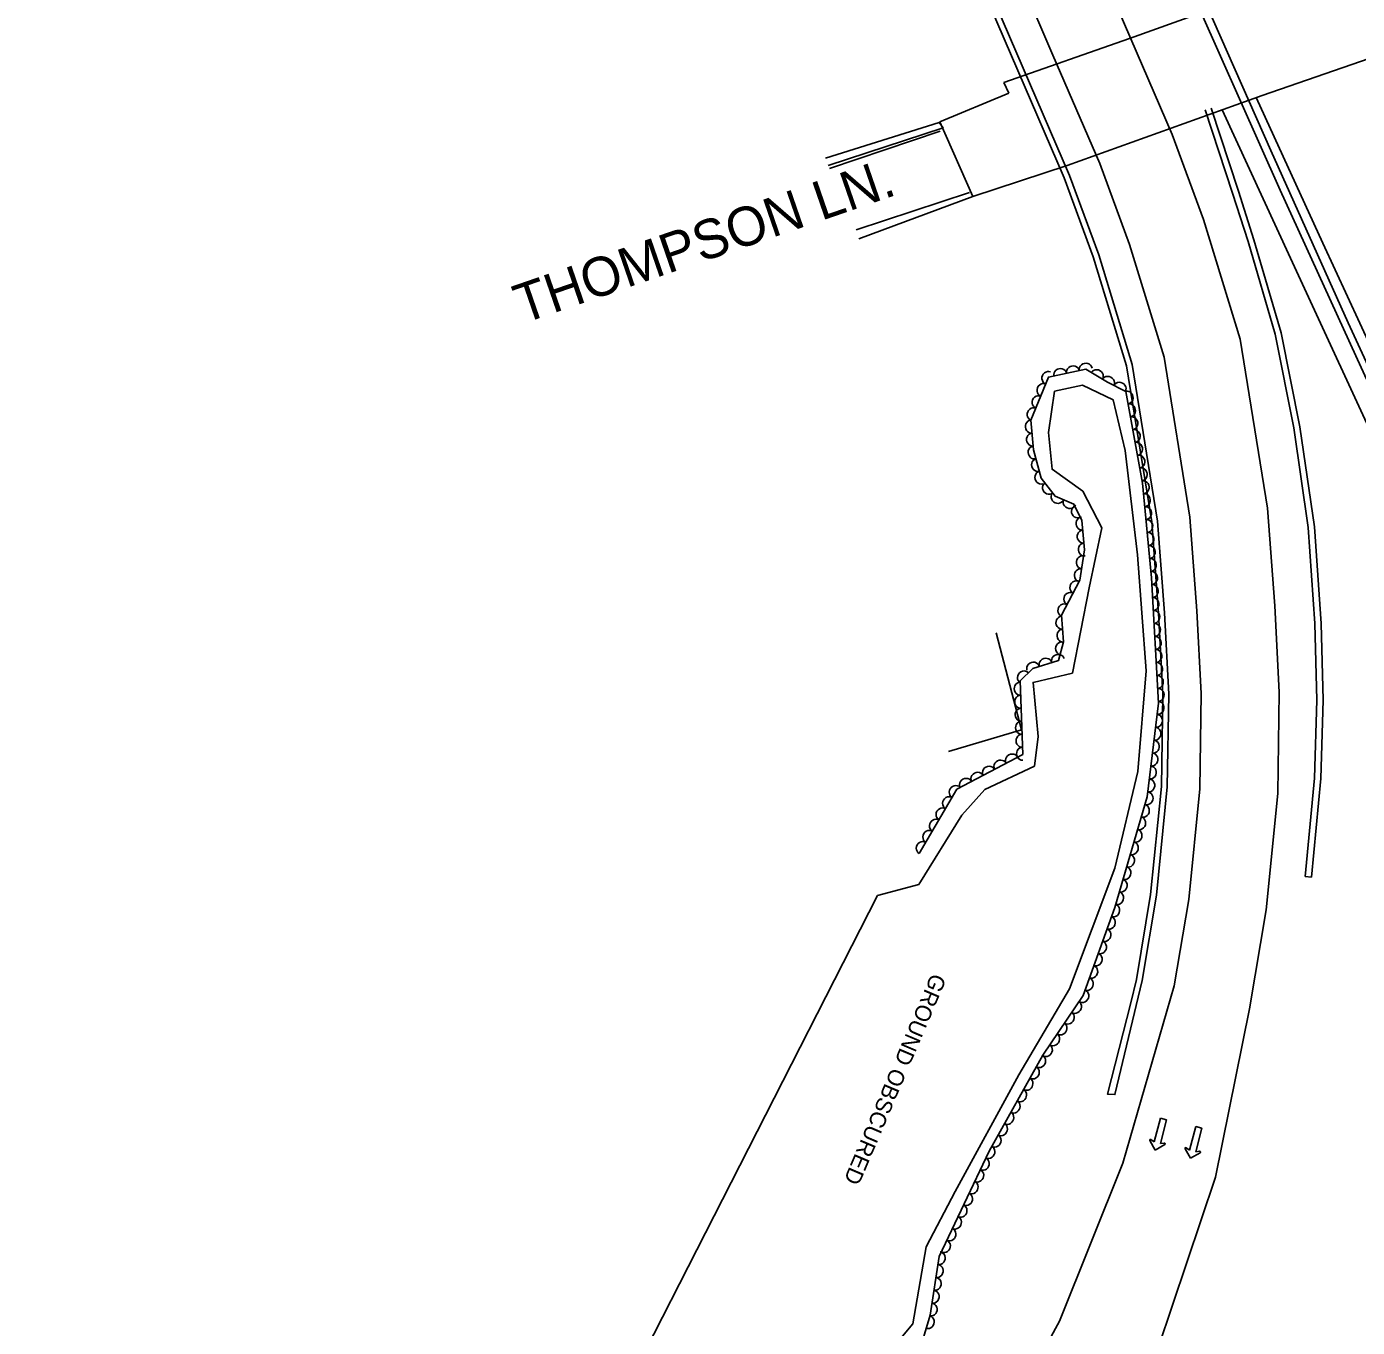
# Model space of a CAD drawing. Extents: x 1746719 to 1766531, y 631721 to 662391.
# Drawn here: x 1754626.9 to 1755036.1, y 647759.3 to 648159.2 of the extents above; entities that cross this region are included whole.
import ezdxf

# ---------------------------------------------------------------- set-up
doc = ezdxf.new("R2010")
doc.units = 0
for name, color, linetype in [('SURVEY - AERIAL SURVEY - Photo Control - Points - Elevations', 7, 'Continuous'), ('SURVEY - AERIAL SURVEY - Photo Control - Points - Locators', 7, 'Continuous'), ('SURVEY - AERIAL SURVEY - Photo Control - Points - Numbers', 7, 'Continuous'), ('SURVEY - AERIAL SURVEY - Photo Control with Text', 7, 'Continuous'), ('SURVEY - CENTERLINE - Existing Roads Curve Text', 7, 'Continuous'), ('SURVEY - CENTERLINE - Existing Roads Text', 7, 'Continuous'), ('SURVEY - CONTROL - Points - Numbers', 7, 'Continuous')]:
    doc.layers.add(name, color=color, linetype=linetype)

msp = doc.modelspace()

# ---------------------------------------------------------------- linework, layer by layer
at = {"layer": 'SURVEY - AERIAL SURVEY - Photo Control - Points - Elevations'}
for points in [[(1754626.92, 649017.27), (1754709.95, 648778.72), (1754733.03, 648713.46), (1754751.76, 648662.58), (1754773.93, 648603.83), (1754794.84, 648551.03), (1754823.16, 648481.11), (1754839.71, 648443.33), (1754863.44, 648389.05), (1754891.92, 648325.15), (1754920.31, 648262.45), (1754945.87, 648203.41), (1754964.57, 648159.87), (1754979.21, 648126.03), (1754988.86, 648099.84), (1755000.1, 648063.05), (1755008.46, 648011.18), (1755010.74, 647981.16), (1755012.12, 647954.58), (1755011.65, 647923.49), (1755008.06, 647887.7), (1755002.99, 647857.3)], [(1754923.83, 648193.91), (1754942.53, 648150.37), (1754956.92, 648117.11), (1754966.11, 648092.18), (1754976.67, 648057.61), (1754984.6, 648008.36), (1754986.79, 647979.62), (1754988.11, 647954.14), (1754987.66, 647924.88), (1754984.26, 647890.87), (1754979.83, 647864.32)], [(1755004.97, 648137.37), (1755025.54, 648092.61), (1755055.82, 648027.06), (1755078.02, 647978.11), (1755103.02, 647921.72), (1755129.6, 647862.19), (1755152.75, 647809.59), (1755172.94, 647764.12)], [(1754994.59, 648133.62), (1755015.55, 648088.01), (1755045.82, 648022.48), (1755067.98, 647973.61), (1755092.97, 647917.25), (1755119.54, 647857.74), (1755142.69, 647805.14), (1755162.88, 647759.66)], [(1754873.78, 648115.58), (1754907.89, 648126.99)], [(1754916.82, 648108.16), (1754881.96, 648096.73)], [(1754979.83, 647864.32), (1754963.96, 647809.85), (1754944.5, 647761.3), (1754906.27, 647690.97), (1754872.82, 647629.82)], [(1755002.99, 647857.3), (1754992.52, 647805.51), (1754974.85, 647753.02), (1754904.16, 647615.22)]]:
    msp.add_lwpolyline(points, dxfattribs=at)
at = {"layer": 'SURVEY - AERIAL SURVEY - Photo Control - Points - Locators'}
for p, q in [((1754973.65, 647816.33), (1754975.56, 647823.6)), ((1754975.56, 647823.6), (1754973.65, 647816.33)), ((1754977.47, 647823.1), (1754975.55, 647815.83)), ((1754977.47, 647823.1), (1754975.55, 647815.83)), ((1754975.56, 647823.6), (1754977.47, 647823.1)), ((1754977.47, 647823.1), (1754975.56, 647823.6)), ((1754984.51, 647813.8), (1754986.42, 647821.08)), ((1754986.42, 647821.08), (1754984.51, 647813.8)), ((1754988.32, 647820.58), (1754986.41, 647813.3)), ((1754988.32, 647820.58), (1754986.41, 647813.3)), ((1754986.42, 647821.08), (1754988.32, 647820.58)), ((1754988.32, 647820.58), (1754986.42, 647821.08)), ((1754974, 647813.83), (1754972.31, 647816.75)), ((1754974, 647813.83), (1754972.31, 647816.75)), ((1754972.67, 647817.07), (1754973.65, 647816.33)), ((1754973.65, 647816.33), (1754972.67, 647817.07)), ((1754976.92, 647815.53), (1754974, 647813.83)), ((1754974, 647813.83), (1754976.92, 647815.53)), ((1754975.55, 647815.83), (1754976.77, 647815.99)), ((1754975.55, 647815.83), (1754976.77, 647815.99)), ((1754984.86, 647811.31), (1754983.17, 647814.23)), ((1754984.86, 647811.31), (1754983.17, 647814.23)), ((1754983.53, 647814.55), (1754984.51, 647813.8)), ((1754984.51, 647813.8), (1754983.53, 647814.55)), ((1754986.41, 647813.3), (1754987.62, 647813.47)), ((1754986.41, 647813.3), (1754987.62, 647813.47)), ((1754987.78, 647813.01), (1754984.86, 647811.31)), ((1754984.86, 647811.31), (1754987.78, 647813.01))]:
    msp.add_line(p, q, dxfattribs=at)
for points in [[(1754989.49, 648166.25), (1755009.5, 648121.07), (1755033.31, 648068.13), (1755056.92, 648017.04), (1755088.07, 647952.49), (1755086.25, 647951.41), (1755076.05, 647972.49), (1755060.21, 648004.32), (1755035.62, 648058.01), (1755012.44, 648108.93), (1754981.51, 648178.28)], [(1754888.59, 647892.11), (1754901.25, 647895.45), (1754914.5, 647916.75), (1754921.56, 647924.64), (1754936.83, 647931.87), (1754937.93, 647941), (1754936.43, 647957.6), (1754948.49, 647960.47), (1754953.64, 647986.68), (1754957.52, 648005.09), (1754951.69, 648016.42), (1754942.28, 648023.12), (1754941.11, 648034.45), (1754943.01, 648047.07), (1754951.65, 648048.92), (1754961.07, 648044.43), (1754964.71, 648028.91), (1754968.52, 647996.83), (1754971.19, 647961.11), (1754968.64, 647930.23), (1754961.51, 647900.54), (1754947.6, 647863.41), (1754932, 647836.97), (1754912.47, 647801.13), (1754903.58, 647784.14), (1754899.41, 647760.42), (1754886.88, 647745.47)], [(1754803.95, 647726.12), (1754888.59, 647892.11)]]:
    msp.add_lwpolyline(points, dxfattribs=at)
for centre, start, end in [((1754972.52, 647816.88), 52.7863, 210.2346), ((1754972.52, 647816.88), 52.7863, 210.2346), ((1754976.8, 647815.75), 300.2346, 97.7278), ((1754976.8, 647815.75), 300.2346, 97.7278), ((1754983.38, 647814.35), 52.7863, 210.2346), ((1754983.38, 647814.35), 52.7863, 210.2346), ((1754987.66, 647813.22), 300.2346, 97.7278), ((1754987.66, 647813.22), 300.2346, 97.7278)]:
    msp.add_arc(centre, 0.246, start, end, dxfattribs=at)
at = {"layer": 'SURVEY - AERIAL SURVEY - Photo Control - Points - Numbers'}
for points in [[(1754914.65, 648189.95), (1754933.35, 648146.41), (1754947.63, 648113.39), (1754956.62, 648088.99), (1754966.91, 648055.34), (1754974.66, 648007.18), (1754976.81, 647978.98), (1754978.11, 647953.96), (1754977.67, 647925.45), (1754974.34, 647892.2), (1754969.96, 647865.96)], [(1754913, 648189.24), (1754931.7, 648145.7), (1754945.96, 648112.73), (1754954.92, 648088.42), (1754965.15, 648054.94), (1754972.88, 648006.97), (1754975.02, 647978.87), (1754976.31, 647953.93), (1754975.88, 647925.55), (1754972.56, 647892.43), (1754968.19, 647866.25)], [(1755020.13, 647897.94), (1755022.96, 647928.14), (1755023.68, 647952.09), (1755023.03, 647975.65), (1755021.04, 648005.16), (1755016.6, 648035.82), (1755010.85, 648064.58), (1755002.5, 648093.09), (1754997.78, 648107.99), (1754989.36, 648133.56)], [(1755022.04, 647897.75), (1755024.87, 647928.02), (1755025.6, 647952.08), (1755024.95, 647975.74), (1755022.95, 648005.36), (1755018.49, 648036.14), (1755012.71, 648065.03), (1755004.33, 648093.64), (1754999.61, 648108.58), (1754991.18, 648134.14)], [(1754872.53, 648118.72), (1754907.57, 648129.73), (1754908.73, 648128.03), (1754873.35, 648116.43)], [(1754882.84, 648093.89), (1754917.86, 648106.97)], [(1755020.13, 647897.94), (1755022.04, 647897.75)], [(1754969.96, 647865.96), (1754961.59, 647830.92), (1754959.33, 647830.98), (1754966.44, 647859.06), (1754968.19, 647866.25)]]:
    msp.add_lwpolyline(points, dxfattribs=at)
at = {"layer": 'SURVEY - AERIAL SURVEY - Photo Control with Text'}
msp.add_lwpolyline([(1754901.38, 647904.98), (1754913.01, 647924.73), (1754933.21, 647935.43), (1754932.41, 647958.05), (1754936.36, 647961.91), (1754944.25, 647964.35), (1754945.79, 647970.07), (1754945.14, 647978.23), (1754950.78, 647989.03), (1754952.23, 647998.38), (1754951.42, 648007.4), (1754948.96, 648012.4), (1754943.18, 648014.84), (1754938.9, 648020.37), (1754936.56, 648029.06), (1754935.74, 648038.17), (1754941.12, 648051.42), (1754952.66, 648053.82), (1754959.25, 648049.86), (1754964.94, 648046.98), (1754970.1, 648018.85), (1754972.8, 647989.72), (1754974.94, 647951.18), (1754971.54, 647922.46), (1754961.5, 647888.43), (1754951.79, 647861.4), (1754939.38, 647843), (1754922.86, 647813.5), (1754907.58, 647781.16), (1754904.74, 647763.08), (1754901.27, 647751.43)], dxfattribs=at)
for centre, major_axis in [((1754948.68, 648052.99), (1.96, 0.41)), ((1754952.6, 648053.8), (1.96, 0.41)), ((1754941.02, 648051.17), (0.75, 1.85)), ((1754944.76, 648052.18), (1.96, 0.41)), ((1754956.04, 648051.79), (1.72, -1.03)), ((1754959.48, 648049.75), (1.78, -0.91)), ((1754939.51, 648047.46), (0.75, 1.85)), ((1754963.04, 648047.94), (1.78, -0.91)), ((1754965.27, 648045.13), (0.36, -1.97)), ((1754936.5, 648040.05), (0.75, 1.85)), ((1754938.01, 648043.75), (0.75, 1.85)), ((1754966, 648041.2), (0.36, -1.97)), ((1754935.92, 648036.2), (-0.18, 1.99)), ((1754966.72, 648037.26), (0.36, -1.97)), ((1754936.28, 648032.22), (-0.18, 1.99)), ((1754967.44, 648033.33), (0.36, -1.97)), ((1754936.78, 648028.26), (-0.52, 1.93)), ((1754968.16, 648029.4), (0.36, -1.97)), ((1754937.82, 648024.4), (-0.52, 1.93)), ((1754968.89, 648025.46), (0.36, -1.97)), ((1754938.86, 648020.54), (-0.52, 1.93)), ((1754969.61, 648021.53), (0.36, -1.97)), ((1754941.25, 648017.34), (-1.22, 1.58)), ((1754970.22, 648017.58), (0.18, -1.99)), ((1754943.95, 648014.51), (-1.84, 0.78)), ((1754947.63, 648012.95), (-1.84, 0.78)), ((1754970.59, 648013.59), (0.18, -1.99)), ((1754950.09, 648010.09), (-0.88, 1.79)), ((1754970.96, 648009.61), (0.18, -1.99)), ((1754951.5, 648006.41), (-0.18, 1.99)), ((1754971.33, 648005.63), (0.18, -1.99)), ((1754951.86, 648002.42), (-0.18, 1.99)), ((1754971.69, 648001.65), (0.18, -1.99)), ((1754952.22, 647998.44), (-0.18, 1.99)), ((1754972.06, 647997.66), (0.18, -1.99)), ((1754951.62, 647994.49), (0.31, 1.98)), ((1754972.43, 647993.68), (0.18, -1.99)), ((1754949.63, 647986.83), (0.93, 1.77)), ((1754951.01, 647990.53), (0.31, 1.98)), ((1754972.8, 647989.7), (0.11, -2)), ((1754947.78, 647983.29), (0.93, 1.77)), ((1754973.02, 647985.7), (0.11, -2)), ((1754945.93, 647979.74), (0.93, 1.77)), ((1754973.24, 647981.71), (0.11, -2)), ((1754945.32, 647975.94), (-0.16, 1.99)), ((1754973.47, 647977.71), (0.11, -2)), ((1754945.64, 647971.95), (-0.16, 1.99)), ((1754973.69, 647973.72), (0.11, -2)), ((1754945.24, 647968.03), (0.52, 1.93)), ((1754973.91, 647969.73), (0.11, -2)), ((1754940.25, 647963.11), (1.91, 0.59)), ((1754944.07, 647964.3), (1.91, 0.59)), ((1754974.13, 647965.73), (0.11, -2)), ((1754933.55, 647959.16), (1.43, 1.4)), ((1754936.43, 647961.93), (1.91, 0.59)), ((1754974.35, 647961.74), (0.11, -2)), ((1754932.49, 647955.64), (-0.07, 2)), ((1754974.58, 647957.75), (0.11, -2)), ((1754932.64, 647951.65), (-0.07, 2)), ((1754974.8, 647953.75), (0.11, -2)), ((1754932.78, 647947.65), (-0.07, 2)), ((1754974.77, 647949.77), (-0.24, -1.99)), ((1754932.92, 647943.65), (-0.07, 2)), ((1754974.3, 647945.79), (-0.24, -1.99)), ((1754933.06, 647939.65), (-0.07, 2)), ((1754973.83, 647941.82), (-0.24, -1.99)), ((1754933.2, 647935.66), (-0.07, 2)), ((1754973.36, 647937.85), (-0.24, -1.99)), ((1754922.8, 647929.92), (1.77, 0.94)), ((1754926.34, 647931.79), (1.77, 0.94)), ((1754929.87, 647933.67), (1.77, 0.94)), ((1754972.42, 647929.9), (-0.24, -1.99)), ((1754972.89, 647933.88), (-0.24, -1.99)), ((1754915.73, 647926.17), (1.77, 0.94)), ((1754919.27, 647928.05), (1.77, 0.94)), ((1754971.95, 647925.93), (-0.24, -1.99)), ((1754912.54, 647923.94), (1.01, 1.72)), ((1754971.4, 647921.98), (-0.57, -1.92)), ((1754910.51, 647920.49), (1.01, 1.72)), ((1754970.26, 647918.14), (-0.57, -1.92)), ((1754906.46, 647913.6), (1.01, 1.72)), ((1754908.48, 647917.05), (1.01, 1.72)), ((1754969.13, 647914.3), (-0.57, -1.92)), ((1754904.43, 647910.15), (1.01, 1.72)), ((1754968, 647910.47), (-0.57, -1.92)), ((1754902.4, 647906.71), (1.01, 1.72)), ((1754966.87, 647906.63), (-0.57, -1.92)), ((1754965.74, 647902.79), (-0.57, -1.92)), ((1754964.6, 647898.96), (-0.57, -1.92)), ((1754963.47, 647895.12), (-0.57, -1.92)), ((1754962.34, 647891.28), (-0.57, -1.92)), ((1754961.15, 647887.47), (-0.68, -1.88)), ((1754959.8, 647883.7), (-0.68, -1.88)), ((1754958.45, 647879.94), (-0.68, -1.88)), ((1754957.09, 647876.17), (-0.68, -1.88)), ((1754954.39, 647868.64), (-0.68, -1.88)), ((1754955.74, 647872.41), (-0.68, -1.88)), ((1754953.04, 647864.88), (-0.68, -1.88)), ((1754951.62, 647861.15), (-1.12, -1.66)), ((1754949.38, 647857.83), (-1.12, -1.66)), ((1754947.15, 647854.52), (-1.12, -1.66)), ((1754944.91, 647851.2), (-1.12, -1.66)), ((1754940.43, 647844.57), (-1.12, -1.66)), ((1754942.67, 647847.89), (-1.12, -1.66)), ((1754938.35, 647841.16), (-0.98, -1.75)), ((1754936.39, 647837.67), (-0.98, -1.75)), ((1754934.44, 647834.18), (-0.98, -1.75)), ((1754932.49, 647830.69), (-0.98, -1.75)), ((1754928.58, 647823.71), (-0.98, -1.75)), ((1754930.53, 647827.2), (-0.98, -1.75)), ((1754926.63, 647820.22), (-0.98, -1.75)), ((1754924.67, 647816.73), (-0.98, -1.75)), ((1754922.74, 647813.23), (-0.85, -1.81)), ((1754921.03, 647809.61), (-0.85, -1.81)), ((1754919.32, 647805.99), (-0.85, -1.81)), ((1754917.61, 647802.38), (-0.85, -1.81)), ((1754914.19, 647795.14), (-0.85, -1.81)), ((1754915.9, 647798.76), (-0.85, -1.81)), ((1754912.48, 647791.53), (-0.85, -1.81)), ((1754910.78, 647787.91), (-0.85, -1.81)), ((1754909.07, 647784.29), (-0.85, -1.81)), ((1754907.5, 647780.63), (-0.31, -1.98)), ((1754906.88, 647776.68), (-0.31, -1.98)), ((1754906.26, 647772.73), (-0.31, -1.98)), ((1754905.64, 647768.78), (-0.31, -1.98)), ((1754905.02, 647764.83), (-0.31, -1.98)), ((1754904.11, 647760.94), (-0.57, -1.92))]:
    msp.add_ellipse(centre, major_axis=major_axis, ratio=0.940188, start_param=0, end_param=3.141593, dxfattribs=at)
at = {"layer": 'SURVEY - CENTERLINE - Existing Roads Curve Text'}
msp.add_lwpolyline([(1754910.41, 647936.33), (1754932.9, 647942.97), (1754925.02, 647972.8)], dxfattribs=at)
at = {"layer": 'SURVEY - CENTERLINE - Existing Roads Text'}
for p, q in [((1754966.01, 648155.54), (1755006.24, 648169.94)), ((1755068.93, 648159.44), (1755006.9, 648138.04)), ((1754927.4, 648142.01), (1754966.01, 648155.54)), ((1754928.99, 648138.74), (1754927.4, 648142.01)), ((1754907.77, 648129.93), (1754928.99, 648138.74)), ((1755006.9, 648138.04), (1754946.92, 648116.5)), ((1754917.86, 648106.97), (1754907.77, 648129.93)), ((1754946.92, 648116.5), (1754917.86, 648106.97))]:
    msp.add_line(p, q, dxfattribs=at)

# ---------------------------------------------------------------- texts
at = {"layer": 'SURVEY - AERIAL SURVEY - Photo Control - Points - Locators'}
msp.add_text('GROUND OBSCURED', height=5, rotation=246.9686, dxfattribs=at).set_placement((1754905.29, 647868.48))
at = {"layer": 'SURVEY - CONTROL - Points - Numbers'}
msp.add_text('THOMPSON LN.', height=12, rotation=19.0344, dxfattribs=at).set_placement((1754779.41, 648067.75))

doc.saveas('drawing.dxf')
